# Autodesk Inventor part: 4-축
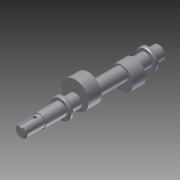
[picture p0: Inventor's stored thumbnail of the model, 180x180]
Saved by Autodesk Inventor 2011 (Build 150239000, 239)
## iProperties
Created: 2014-12
Part Number: 4-축
Document SubType Name: Modeling
Designer: user
Density: 1 g/cm^3
Author: user
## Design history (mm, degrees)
sketch "스케치2"
  geometry: L1 (-90, 0)-(90, 0); L2 (-90, 0)-(-90, 7.5); L3 (-90, 7.5)-(-66, 7.5); L4 (-66, 7.5)-(-66, 8.5); L5 (-66, 8.5)-(-39, 8.5); L6 (-39, 8.5)-(-39, 13); L7 (-39, 13)-(-34, 13); L8 (-34, 13)-(-34, 8.5); L9 (-34, 8.5)-(72, 8.5); L10 (72, 8.5)-(72, 13); L11 (72, 13)-(77, 13); L12 (77, 13)-(77, 8.5); L13 (77, 8.5)-(90, 8.5); L14 (90, 8.5)-(90, 0); 2 further points
  constraints: 28 end point, 11 parallel, 2 perpendicular, 1 coincident, 1 horizontal, 1 midpoint
  dimensions: "d0" = 180 distance of L1.start L1.end; "d1" = 17 diameter of L13 L1; "d2" = 26 diameter of L11 L1; "d3" = 13 distance of L12.end L13.end; "d4" = 5 distance of L10.end L11.end; "d5" = 15 diameter of L3 L1; "d6" = 17 diameter of L5 L1; "d7" = 26 diameter of L7 L1; "d8" = 24 distance of L2.end L3.end; "d9" = 27 distance of L4.end L5.end; "d10" = 5 distance of L6.end L7.end; "d11" = 17 diameter of L9 L1
revolve "회전1" sketch "스케치2" stored, may be unused: angle "d12" = 90 deg
node "작업 평면1"
sketch "스케치3"
  geometry: C1 r 17.5 at (0, 6); 1 further point
  constraints: 1 centre point, 1 vertical alignment
  dimensions: "d14" = 35 diameter of C1; "d15" = 6 distance of point (0, 0) C1.centre
extrude "돌출1" join sketch "스케치3" distance "d16" = 17; taper "d17" = 0 deg
node "작업 평면2"
sketch "스케치4"
  geometry: C1 r 15 at (0, -5); 1 further point
  constraints: 1 centre point, 1 vertical alignment
  dimensions: "d19" = 30 diameter of C1; "d20" = 5 distance of C1.centre point (0, 0)
extrude "돌출2" join sketch "스케치4" distance "d21" = 17; taper "d22" = 0 deg
node "작업 평면3"
sketch "스케치5"
  geometry: L1 (7.5, 12)-(-7.5, 12) reference; L2 (7.5, -12)-(-7.5, -12) reference; L3 (-2.5, 5.5)-(-2.5, -12); L4 (2.5, 5.5)-(2.5, -12); A1 r 2.5 centre (0, 5.5) between (2.5, 5.5) and (-2.5, 5.5); 2 further points
  constraints: 4 end point, 2 perpendicular, 2 point on circle, 2 point on line, 2 tangent, 1 centre point, 1 midpoint, 1 vertical alignment
  dimensions: "d23" = 5 diameter of A1; "d24" = 20 dimension on A1 L2
extrude "돌출3" cut sketch "스케치5" distance "d25" = 3; taper "d26" = 0 deg
chamfer "모따기1" distance "d27" = 1; stored, may be unused: second distance "d28" = 2, angle "d29" = 45 deg
node "솔리드1"
node "투영된 루프1"
other parameters: "d13" = 14.5, "d18" = 14.5
